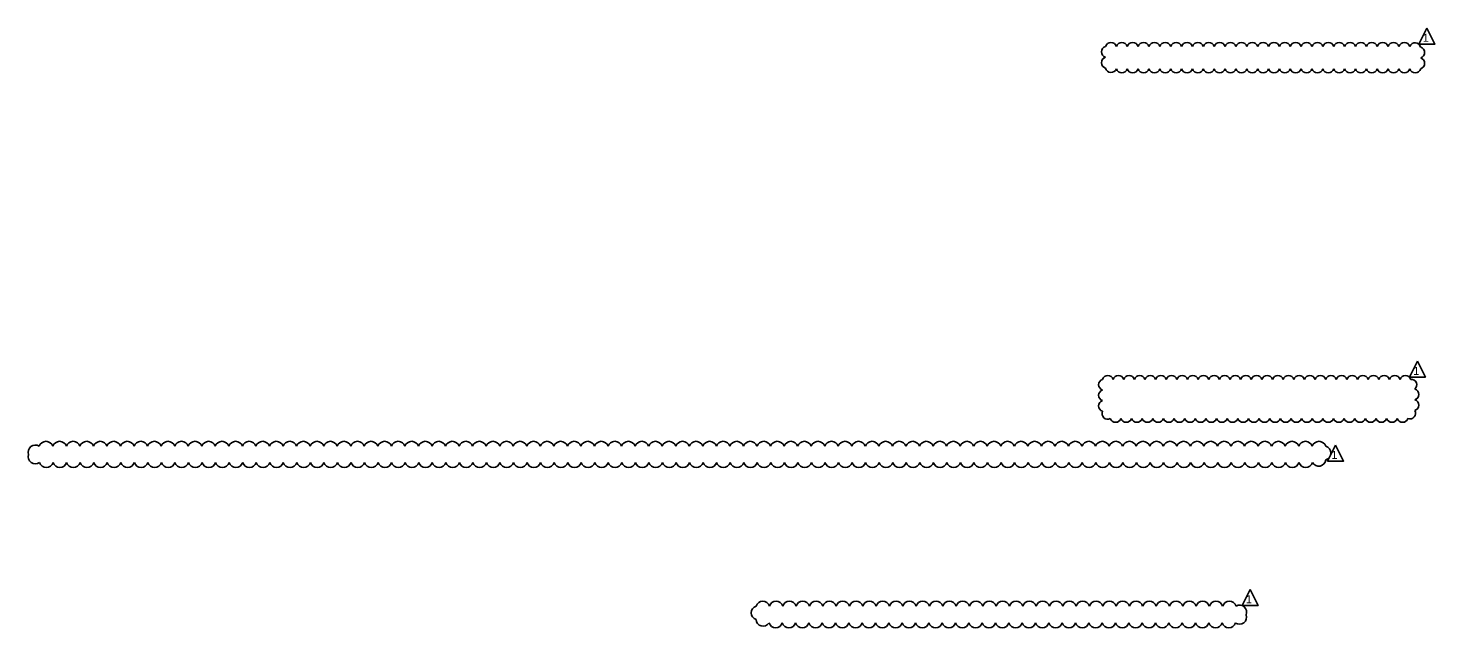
# Model space of a CAD drawing. Extents: x 0 to 76.3, y 0 to 22.
# Drawn here: x 51.66 to 76.27, y 1.24 to 11.74 of the extents above; entities that cross this region are included whole.
import ezdxf

# ---------------------------------------------------------------- set-up
doc = ezdxf.new("R2010")
doc.units = 0
doc.layers.add('SH_Text', color=7, linetype='Continuous')

msp = doc.modelspace()

# ---------------------------------------------------------------- linework, layer by layer
at = {"layer": 'SH_Text'}
for points in [[(76.126, 11.739), (75.986, 11.459), (76.266, 11.459)], [(75.96, 5.91), (75.82, 5.63), (76.1, 5.63)], [(74.529, 4.44), (74.389, 4.16), (74.669, 4.16)], [(73.035, 1.913), (72.895, 1.633), (73.175, 1.633)]]:
    msp.add_lwpolyline(points, close=True, dxfattribs=at)
for centre, radius, start, end in [((70.536, 11.324), 0.0997, 107.5, 252.5), ((70.601, 11.389), 0.0997, 17.5, 162.5), ((70.791, 11.389), 0.0997, 17.5, 162.5), ((70.981, 11.389), 0.0997, 17.5, 162.5), ((71.171, 11.389), 0.0997, 17.5, 162.5), ((71.361, 11.389), 0.0997, 17.5, 162.5), ((71.551, 11.389), 0.0997, 17.5, 162.5), ((71.741, 11.389), 0.0997, 17.5, 162.5), ((71.931, 11.389), 0.0997, 17.5, 162.5), ((72.121, 11.389), 0.0997, 17.5, 162.5), ((72.312, 11.389), 0.0997, 17.5, 162.5), ((72.502, 11.389), 0.0997, 17.5, 162.5), ((72.692, 11.389), 0.0997, 17.5, 162.5), ((72.882, 11.389), 0.0997, 17.5, 162.5), ((73.072, 11.389), 0.0997, 17.5, 162.5), ((73.262, 11.389), 0.0997, 17.5, 162.5), ((73.452, 11.389), 0.0997, 17.5, 162.5), ((73.642, 11.389), 0.0997, 17.5, 162.5), ((73.832, 11.389), 0.0997, 17.5, 162.5), ((74.022, 11.389), 0.0997, 17.5, 162.5), ((74.213, 11.389), 0.0997, 17.5, 162.5), ((74.403, 11.389), 0.0997, 17.5, 162.5), ((74.593, 11.389), 0.0997, 17.5, 162.5), ((74.783, 11.389), 0.0997, 17.5, 162.5), ((74.973, 11.389), 0.0997, 17.5, 162.5), ((75.163, 11.389), 0.0997, 17.5, 162.5), ((75.353, 11.389), 0.0997, 17.5, 162.5), ((75.543, 11.389), 0.0997, 17.5, 162.5), ((75.733, 11.389), 0.0997, 17.5, 162.5), ((75.921, 11.383), 0.0998, 13.8228, 158.8228), ((75.988, 11.312), 0.0996, 287.5, 72.5), ((70.536, 11.134), 0.0996, 107.5, 252.5), ((75.988, 11.122), 0.0997, 287.5, 72.5), ((70.603, 11.063), 0.0998, 193.8228, 338.8228), ((70.791, 11.057), 0.0997, 197.5, 342.5), ((70.981, 11.057), 0.0997, 197.5, 342.5), ((71.171, 11.057), 0.0997, 197.5, 342.5), ((71.361, 11.057), 0.0997, 197.5, 342.5), ((71.551, 11.057), 0.0997, 197.5, 342.5), ((71.741, 11.057), 0.0997, 197.5, 342.5), ((71.931, 11.057), 0.0997, 197.5, 342.5), ((72.121, 11.057), 0.0997, 197.5, 342.5), ((72.311, 11.057), 0.0997, 197.5, 342.5), ((72.501, 11.057), 0.0997, 197.5, 342.5), ((72.692, 11.057), 0.0997, 197.5, 342.5), ((72.882, 11.057), 0.0997, 197.5, 342.5), ((73.072, 11.057), 0.0997, 197.5, 342.5), ((73.262, 11.057), 0.0997, 197.5, 342.5), ((73.452, 11.057), 0.0997, 197.5, 342.5), ((73.642, 11.057), 0.0997, 197.5, 342.5), ((73.832, 11.057), 0.0997, 197.5, 342.5), ((74.022, 11.057), 0.0997, 197.5, 342.5), ((74.212, 11.057), 0.0997, 197.5, 342.5), ((74.402, 11.057), 0.0997, 197.5, 342.5), ((74.593, 11.057), 0.0997, 197.5, 342.5), ((74.783, 11.057), 0.0997, 197.5, 342.5), ((74.973, 11.057), 0.0997, 197.5, 342.5), ((75.163, 11.057), 0.0997, 197.5, 342.5), ((75.353, 11.057), 0.0997, 197.5, 342.5), ((75.543, 11.057), 0.0997, 197.5, 342.5), ((75.733, 11.057), 0.0997, 197.5, 342.5), ((75.923, 11.057), 0.0997, 197.5, 342.5), ((70.546, 5.562), 0.0975, 17.5, 162.5), ((70.731, 5.562), 0.0975, 17.5, 162.5), ((70.917, 5.562), 0.0975, 17.5, 162.5), ((71.103, 5.562), 0.0975, 17.5, 162.5), ((71.289, 5.562), 0.0975, 17.5, 162.5), ((71.475, 5.562), 0.0975, 17.5, 162.5), ((71.661, 5.562), 0.0975, 17.5, 162.5), ((71.847, 5.562), 0.0975, 17.5, 162.5), ((72.033, 5.562), 0.0975, 17.5, 162.5), ((72.219, 5.562), 0.0975, 17.5, 162.5), ((72.405, 5.562), 0.0975, 17.5, 162.5), ((72.59, 5.562), 0.0975, 17.5, 162.5), ((72.776, 5.562), 0.0975, 17.5, 162.5), ((72.962, 5.562), 0.0975, 17.5, 162.5), ((73.148, 5.562), 0.0975, 17.5, 162.5), ((73.334, 5.562), 0.0975, 17.5, 162.5), ((73.52, 5.562), 0.0975, 17.5, 162.5), ((73.706, 5.562), 0.0975, 17.5, 162.5), ((73.892, 5.562), 0.0975, 17.5, 162.5), ((74.078, 5.562), 0.0975, 17.5, 162.5), ((74.264, 5.562), 0.0975, 17.5, 162.5), ((74.449, 5.562), 0.0975, 17.5, 162.5), ((74.635, 5.562), 0.0975, 17.5, 162.5), ((74.821, 5.562), 0.0975, 17.5, 162.5), ((75.007, 5.562), 0.0975, 17.5, 162.5), ((75.193, 5.562), 0.0975, 17.5, 162.5), ((75.379, 5.562), 0.0975, 17.5, 162.5), ((75.565, 5.562), 0.0975, 17.5, 162.5), ((75.751, 5.562), 0.0975, 17.5, 162.5), ((70.482, 5.498), 0.0975, 107.5, 252.5), ((75.853, 5.494), 0.0974, 310.3764, 95.3764), ((75.887, 5.327), 0.0975, 287.5, 72.5), ((70.482, 5.312), 0.0975, 107.5, 252.5), ((70.482, 5.126), 0.0975, 107.5, 252.5), ((75.887, 5.141), 0.0974, 287.5, 72.5), ((70.541, 4.992), 0.0974, 154.8347, 299.8347), ((75.833, 4.997), 0.0975, 246.7274, 31.7274), ((70.682, 4.937), 0.0975, 197.5, 342.5), ((70.868, 4.937), 0.0975, 197.5, 342.5), ((71.054, 4.937), 0.0975, 197.5, 342.5), ((71.24, 4.937), 0.0975, 197.5, 342.5), ((71.426, 4.937), 0.0975, 197.5, 342.5), ((71.612, 4.937), 0.0975, 197.5, 342.5), ((71.798, 4.937), 0.0975, 197.5, 342.5), ((71.984, 4.937), 0.0975, 197.5, 342.5), ((72.169, 4.937), 0.0975, 197.5, 342.5), ((72.355, 4.937), 0.0975, 197.5, 342.5), ((72.541, 4.937), 0.0975, 197.5, 342.5), ((72.727, 4.937), 0.0975, 197.5, 342.5), ((72.913, 4.937), 0.0975, 197.5, 342.5), ((73.099, 4.937), 0.0975, 197.5, 342.5), ((73.285, 4.937), 0.0975, 197.5, 342.5), ((73.471, 4.937), 0.0975, 197.5, 342.5), ((73.657, 4.937), 0.0975, 197.5, 342.5), ((73.843, 4.937), 0.0975, 197.5, 342.5), ((74.029, 4.937), 0.0975, 197.5, 342.5), ((74.214, 4.937), 0.0975, 197.5, 342.5), ((74.4, 4.937), 0.0975, 197.5, 342.5), ((74.586, 4.937), 0.0975, 197.5, 342.5), ((74.772, 4.937), 0.0975, 197.5, 342.5), ((74.958, 4.937), 0.0975, 197.5, 342.5), ((75.144, 4.937), 0.0975, 197.5, 342.5), ((75.33, 4.937), 0.0975, 197.5, 342.5), ((75.516, 4.937), 0.0975, 197.5, 342.5), ((75.702, 4.937), 0.0975, 197.5, 342.5), ((51.785, 4.318), 0.124, 55.2414, 200.2414), ((51.974, 4.383), 0.124, 17.5, 162.5), ((52.211, 4.383), 0.124, 17.5, 162.5), ((52.448, 4.383), 0.124, 17.5, 162.5), ((52.685, 4.383), 0.124, 17.5, 162.5), ((52.922, 4.383), 0.124, 17.5, 162.5), ((53.158, 4.383), 0.124, 17.5, 162.5), ((53.395, 4.383), 0.124, 17.5, 162.5), ((53.632, 4.383), 0.124, 17.5, 162.5), ((53.869, 4.383), 0.124, 17.5, 162.5), ((54.106, 4.383), 0.124, 17.5, 162.5), ((54.343, 4.383), 0.124, 17.5, 162.5), ((54.58, 4.383), 0.124, 17.5, 162.5), ((54.817, 4.383), 0.124, 17.5, 162.5), ((55.053, 4.383), 0.124, 17.5, 162.5), ((55.29, 4.383), 0.124, 17.5, 162.5), ((55.527, 4.383), 0.124, 17.5, 162.5), ((55.764, 4.383), 0.124, 17.5, 162.5), ((56.001, 4.383), 0.124, 17.5, 162.5), ((56.238, 4.383), 0.124, 17.5, 162.5), ((56.475, 4.383), 0.124, 17.5, 162.5), ((56.712, 4.383), 0.124, 17.5, 162.5), ((56.948, 4.383), 0.124, 17.5, 162.5), ((57.185, 4.383), 0.124, 17.5, 162.5), ((57.422, 4.383), 0.124, 17.5, 162.5), ((57.659, 4.383), 0.124, 17.5, 162.5), ((57.896, 4.383), 0.124, 17.5, 162.5), ((58.133, 4.383), 0.124, 17.5, 162.5), ((58.37, 4.383), 0.124, 17.5, 162.5), ((58.607, 4.383), 0.124, 17.5, 162.5), ((58.843, 4.383), 0.124, 17.5, 162.5), ((59.08, 4.383), 0.124, 17.5, 162.5), ((59.317, 4.383), 0.124, 17.5, 162.5), ((59.554, 4.383), 0.124, 17.5, 162.5), ((59.791, 4.383), 0.124, 17.5, 162.5), ((60.028, 4.383), 0.124, 17.5, 162.5), ((60.265, 4.383), 0.124, 17.5, 162.5), ((60.501, 4.383), 0.124, 17.5, 162.5), ((60.738, 4.383), 0.124, 17.5, 162.5), ((60.975, 4.383), 0.124, 17.5, 162.5), ((61.212, 4.383), 0.124, 17.5, 162.5), ((61.449, 4.383), 0.124, 17.5, 162.5), ((61.686, 4.383), 0.124, 17.5, 162.5), ((61.923, 4.383), 0.124, 17.5, 162.5), ((62.16, 4.383), 0.124, 17.5, 162.5), ((62.396, 4.383), 0.124, 17.5, 162.5), ((62.633, 4.383), 0.124, 17.5, 162.5), ((62.87, 4.383), 0.124, 17.5, 162.5), ((63.107, 4.383), 0.124, 17.5, 162.5), ((63.344, 4.383), 0.124, 17.5, 162.5), ((63.581, 4.383), 0.124, 17.5, 162.5), ((63.818, 4.383), 0.124, 17.5, 162.5), ((64.055, 4.383), 0.124, 17.5, 162.5), ((64.291, 4.383), 0.124, 17.5, 162.5), ((64.528, 4.383), 0.124, 17.5, 162.5), ((64.765, 4.383), 0.124, 17.5, 162.5), ((65.002, 4.383), 0.124, 17.5, 162.5), ((65.239, 4.383), 0.124, 17.5, 162.5), ((65.476, 4.383), 0.124, 17.5, 162.5), ((65.713, 4.383), 0.124, 17.5, 162.5), ((65.95, 4.383), 0.124, 17.5, 162.5), ((66.186, 4.383), 0.124, 17.5, 162.5), ((66.423, 4.383), 0.124, 17.5, 162.5), ((66.66, 4.383), 0.124, 17.5, 162.5), ((66.897, 4.383), 0.124, 17.5, 162.5), ((67.134, 4.383), 0.124, 17.5, 162.5), ((67.371, 4.383), 0.124, 17.5, 162.5), ((67.608, 4.383), 0.124, 17.5, 162.5), ((67.845, 4.383), 0.124, 17.5, 162.5), ((68.081, 4.383), 0.124, 17.5, 162.5), ((68.318, 4.383), 0.124, 17.5, 162.5), ((68.555, 4.383), 0.124, 17.5, 162.5), ((68.792, 4.383), 0.124, 17.5, 162.5), ((69.029, 4.383), 0.124, 17.5, 162.5), ((69.266, 4.383), 0.124, 17.5, 162.5), ((69.503, 4.383), 0.124, 17.5, 162.5), ((69.74, 4.383), 0.124, 17.5, 162.5), ((69.976, 4.383), 0.124, 17.5, 162.5), ((70.213, 4.383), 0.124, 17.5, 162.5), ((70.45, 4.383), 0.124, 17.5, 162.5), ((70.687, 4.383), 0.124, 17.5, 162.5), ((70.924, 4.383), 0.124, 17.5, 162.5), ((71.161, 4.383), 0.124, 17.5, 162.5), ((71.398, 4.383), 0.124, 17.5, 162.5), ((71.635, 4.383), 0.124, 17.5, 162.5), ((71.871, 4.383), 0.124, 17.5, 162.5), ((72.108, 4.383), 0.124, 17.5, 162.5), ((72.345, 4.383), 0.124, 17.5, 162.5), ((72.582, 4.383), 0.124, 17.5, 162.5), ((72.819, 4.383), 0.124, 17.5, 162.5), ((73.056, 4.383), 0.124, 17.5, 162.5), ((73.293, 4.383), 0.124, 17.5, 162.5), ((73.53, 4.383), 0.124, 17.5, 162.5), ((73.766, 4.383), 0.124, 17.5, 162.5), ((74.003, 4.383), 0.124, 17.5, 162.5), ((74.24, 4.383), 0.124, 17.5, 162.5), ((51.786, 4.236), 0.124, 161.579, 306.579), ((74.235, 4.196), 0.124, 208.9586, 353.9586), ((74.321, 4.302), 0.124, 287.5, 72.5), ((51.979, 4.173), 0.124, 197.5, 342.5), ((52.216, 4.173), 0.124, 197.5, 342.5), ((52.452, 4.173), 0.124, 197.5, 342.5), ((52.689, 4.173), 0.124, 197.5, 342.5), ((52.926, 4.173), 0.124, 197.5, 342.5), ((53.163, 4.173), 0.124, 197.5, 342.5), ((53.4, 4.173), 0.124, 197.5, 342.5), ((53.637, 4.173), 0.124, 197.5, 342.5), ((53.874, 4.173), 0.124, 197.5, 342.5), ((54.111, 4.173), 0.124, 197.5, 342.5), ((54.347, 4.173), 0.124, 197.5, 342.5), ((54.584, 4.173), 0.124, 197.5, 342.5), ((54.821, 4.173), 0.124, 197.5, 342.5), ((55.058, 4.173), 0.124, 197.5, 342.5), ((55.295, 4.173), 0.124, 197.5, 342.5), ((55.532, 4.173), 0.124, 197.5, 342.5), ((55.769, 4.173), 0.124, 197.5, 342.5), ((56.006, 4.173), 0.124, 197.5, 342.5), ((56.242, 4.173), 0.124, 197.5, 342.5), ((56.479, 4.173), 0.124, 197.5, 342.5), ((56.716, 4.173), 0.124, 197.5, 342.5), ((56.953, 4.173), 0.124, 197.5, 342.5), ((57.19, 4.173), 0.124, 197.5, 342.5), ((57.427, 4.173), 0.124, 197.5, 342.5), ((57.664, 4.173), 0.124, 197.5, 342.5), ((57.901, 4.173), 0.124, 197.5, 342.5), ((58.137, 4.173), 0.124, 197.5, 342.5), ((58.374, 4.173), 0.124, 197.5, 342.5), ((58.611, 4.173), 0.124, 197.5, 342.5), ((58.848, 4.173), 0.124, 197.5, 342.5), ((59.085, 4.173), 0.124, 197.5, 342.5), ((59.322, 4.173), 0.124, 197.5, 342.5), ((59.559, 4.173), 0.124, 197.5, 342.5), ((59.796, 4.173), 0.124, 197.5, 342.5), ((60.032, 4.173), 0.124, 197.5, 342.5), ((60.269, 4.173), 0.124, 197.5, 342.5), ((60.506, 4.173), 0.124, 197.5, 342.5), ((60.743, 4.173), 0.124, 197.5, 342.5), ((60.98, 4.173), 0.124, 197.5, 342.5), ((61.217, 4.173), 0.124, 197.5, 342.5), ((61.454, 4.173), 0.124, 197.5, 342.5), ((61.691, 4.173), 0.124, 197.5, 342.5), ((61.927, 4.173), 0.124, 197.5, 342.5), ((62.164, 4.173), 0.124, 197.5, 342.5), ((62.401, 4.173), 0.124, 197.5, 342.5), ((62.638, 4.173), 0.124, 197.5, 342.5), ((62.875, 4.173), 0.124, 197.5, 342.5), ((63.112, 4.173), 0.124, 197.5, 342.5), ((63.349, 4.173), 0.124, 197.5, 342.5), ((63.586, 4.173), 0.124, 197.5, 342.5), ((63.822, 4.173), 0.124, 197.5, 342.5), ((64.059, 4.173), 0.124, 197.5, 342.5), ((64.296, 4.173), 0.124, 197.5, 342.5), ((64.533, 4.173), 0.124, 197.5, 342.5), ((64.77, 4.173), 0.124, 197.5, 342.5), ((65.007, 4.173), 0.124, 197.5, 342.5), ((65.244, 4.173), 0.124, 197.5, 342.5), ((65.481, 4.173), 0.124, 197.5, 342.5), ((65.717, 4.173), 0.124, 197.5, 342.5), ((65.954, 4.173), 0.124, 197.5, 342.5), ((66.191, 4.173), 0.124, 197.5, 342.5), ((66.428, 4.173), 0.124, 197.5, 342.5), ((66.665, 4.173), 0.124, 197.5, 342.5), ((66.902, 4.173), 0.124, 197.5, 342.5), ((67.139, 4.173), 0.124, 197.5, 342.5), ((67.376, 4.173), 0.124, 197.5, 342.5), ((67.612, 4.173), 0.124, 197.5, 342.5), ((67.849, 4.173), 0.124, 197.5, 342.5), ((68.086, 4.173), 0.124, 197.5, 342.5), ((68.323, 4.173), 0.124, 197.5, 342.5), ((68.56, 4.173), 0.124, 197.5, 342.5), ((68.797, 4.173), 0.124, 197.5, 342.5), ((69.034, 4.173), 0.124, 197.5, 342.5), ((69.271, 4.173), 0.124, 197.5, 342.5), ((69.507, 4.173), 0.124, 197.5, 342.5), ((69.744, 4.173), 0.124, 197.5, 342.5), ((69.981, 4.173), 0.124, 197.5, 342.5), ((70.218, 4.173), 0.124, 197.5, 342.5), ((70.455, 4.173), 0.124, 197.5, 342.5), ((70.692, 4.173), 0.124, 197.5, 342.5), ((70.929, 4.173), 0.124, 197.5, 342.5), ((71.166, 4.173), 0.124, 197.5, 342.5), ((71.402, 4.173), 0.124, 197.5, 342.5), ((71.639, 4.173), 0.124, 197.5, 342.5), ((71.876, 4.173), 0.124, 197.5, 342.5), ((72.113, 4.173), 0.124, 197.5, 342.5), ((72.35, 4.173), 0.124, 197.5, 342.5), ((72.587, 4.173), 0.124, 197.5, 342.5), ((72.824, 4.173), 0.124, 197.5, 342.5), ((73.061, 4.173), 0.124, 197.5, 342.5), ((73.297, 4.173), 0.124, 197.5, 342.5), ((73.534, 4.173), 0.124, 197.5, 342.5), ((73.771, 4.173), 0.124, 197.5, 342.5), ((74.008, 4.173), 0.124, 197.5, 342.5), ((64.431, 1.505), 0.122, 107.5, 252.5), ((64.511, 1.585), 0.122, 17.5, 162.5), ((64.744, 1.585), 0.122, 17.5, 162.5), ((64.977, 1.585), 0.122, 17.5, 162.5), ((65.21, 1.585), 0.122, 17.5, 162.5), ((65.443, 1.585), 0.122, 17.5, 162.5), ((65.677, 1.585), 0.122, 17.5, 162.5), ((65.91, 1.585), 0.122, 17.5, 162.5), ((66.143, 1.585), 0.122, 17.5, 162.5), ((66.376, 1.585), 0.122, 17.5, 162.5), ((66.609, 1.585), 0.122, 17.5, 162.5), ((66.842, 1.585), 0.122, 17.5, 162.5), ((67.076, 1.585), 0.122, 17.5, 162.5), ((67.309, 1.585), 0.122, 17.5, 162.5), ((67.542, 1.585), 0.122, 17.5, 162.5), ((67.775, 1.585), 0.122, 17.5, 162.5), ((68.008, 1.585), 0.122, 17.5, 162.5), ((68.241, 1.585), 0.122, 17.5, 162.5), ((68.475, 1.585), 0.122, 17.5, 162.5), ((68.708, 1.585), 0.122, 17.5, 162.5), ((68.941, 1.585), 0.122, 17.5, 162.5), ((69.174, 1.585), 0.122, 17.5, 162.5), ((69.407, 1.585), 0.122, 17.5, 162.5), ((69.64, 1.585), 0.122, 17.5, 162.5), ((69.874, 1.585), 0.122, 17.5, 162.5), ((70.107, 1.585), 0.122, 17.5, 162.5), ((70.34, 1.585), 0.122, 17.5, 162.5), ((70.573, 1.585), 0.122, 17.5, 162.5), ((70.806, 1.585), 0.122, 17.5, 162.5), ((71.039, 1.585), 0.122, 17.5, 162.5), ((71.273, 1.585), 0.122, 17.5, 162.5), ((71.506, 1.585), 0.122, 17.5, 162.5), ((71.739, 1.585), 0.122, 17.5, 162.5), ((71.972, 1.585), 0.122, 17.5, 162.5), ((72.205, 1.585), 0.122, 17.5, 162.5), ((72.438, 1.585), 0.122, 17.5, 162.5), ((72.672, 1.585), 0.122, 17.5, 162.5), ((72.852, 1.518), 0.122, 336.6684, 121.6684), ((64.516, 1.393), 0.122, 182.1243, 327.1243), ((64.736, 1.364), 0.122, 197.5, 342.5), ((64.969, 1.364), 0.122, 197.5, 342.5), ((65.202, 1.364), 0.122, 197.5, 342.5), ((65.435, 1.364), 0.122, 197.5, 342.5), ((65.668, 1.364), 0.122, 197.5, 342.5), ((65.901, 1.364), 0.122, 197.5, 342.5), ((66.135, 1.364), 0.122, 197.5, 342.5), ((66.368, 1.364), 0.122, 197.5, 342.5), ((66.601, 1.364), 0.122, 197.5, 342.5), ((66.834, 1.364), 0.122, 197.5, 342.5), ((67.067, 1.364), 0.122, 197.5, 342.5), ((67.3, 1.364), 0.122, 197.5, 342.5), ((67.534, 1.364), 0.122, 197.5, 342.5), ((67.767, 1.364), 0.122, 197.5, 342.5), ((68, 1.364), 0.122, 197.5, 342.5), ((68.233, 1.364), 0.122, 197.5, 342.5), ((68.466, 1.364), 0.122, 197.5, 342.5), ((68.699, 1.364), 0.122, 197.5, 342.5), ((68.933, 1.364), 0.122, 197.5, 342.5), ((69.166, 1.364), 0.122, 197.5, 342.5), ((69.399, 1.364), 0.122, 197.5, 342.5), ((69.632, 1.364), 0.122, 197.5, 342.5), ((69.865, 1.364), 0.122, 197.5, 342.5), ((70.098, 1.364), 0.122, 197.5, 342.5), ((70.332, 1.364), 0.122, 197.5, 342.5), ((70.565, 1.364), 0.122, 197.5, 342.5), ((70.798, 1.364), 0.122, 197.5, 342.5), ((71.031, 1.364), 0.122, 197.5, 342.5), ((71.264, 1.364), 0.122, 197.5, 342.5), ((71.497, 1.364), 0.122, 197.5, 342.5), ((71.73, 1.364), 0.122, 197.5, 342.5), ((71.964, 1.364), 0.122, 197.5, 342.5), ((72.197, 1.364), 0.122, 197.5, 342.5), ((72.43, 1.364), 0.122, 197.5, 342.5), ((72.663, 1.364), 0.122, 197.5, 342.5), ((72.85, 1.427), 0.122, 235.1854, 20.1854)]:
    msp.add_arc(centre, radius, start, end, dxfattribs=at)

# ---------------------------------------------------------------- texts
for p in [(76.055, 11.499), (75.888, 5.67), (74.457, 4.2), (72.963, 1.673)]:
    msp.add_text('1', height=0.14, dxfattribs=at).set_placement(p)

doc.saveas('drawing.dxf')
